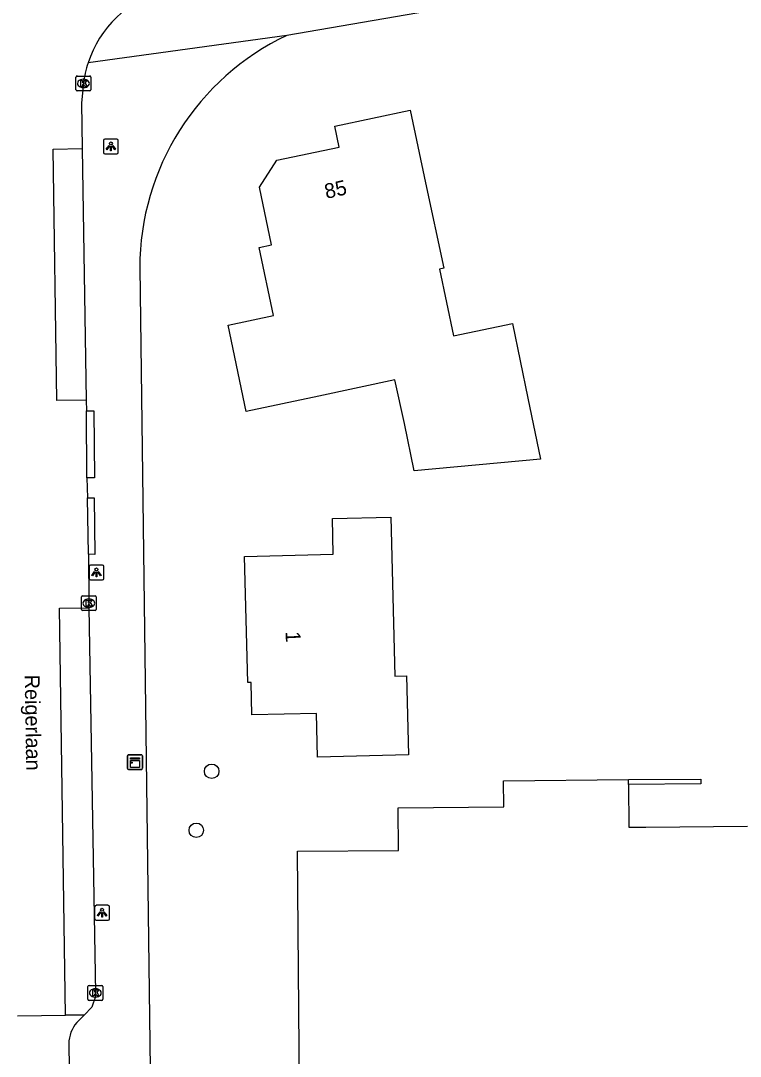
# Model space of a CAD drawing. Extents: x 161772 to 163123, y 383092 to 383917.
# Drawn here: x 162280 to 162328.5, y 383555.7 to 383625.5 of the extents above; entities that cross this region are included whole.
import ezdxf

# ---------------------------------------------------------------- set-up
doc = ezdxf.new("R2010")
doc.units = 0
for name, color, linetype in [('IMGEO_Boom', 7, 'Continuous'), ('IMGEO_Kast', 7, 'Continuous'), ('IMGEO_Kolk', 7, 'Continuous'), ('IMGEO_Lichtpunt', 7, 'Continuous'), ('IMGEO_Muur', 7, 'Continuous'), ('IMGEO_Openbare_ruimte_label', 7, 'Continuous'), ('IMGEO_Pand', 7, 'Continuous'), ('IMGEO_Pand_nummerreeks', 7, 'Continuous'), ('IMGEO_Rijbaan_lokaal_gesloten', 7, 'Continuous'), ('IMGEO_Rijbaan_lokaal_open', 7, 'Continuous'), ('IMGEO_Voetpad_open', 7, 'Continuous')]:
    doc.layers.add(name, color=color, linetype=linetype)

msp = doc.modelspace()

# ---------------------------------------------------------------- linework, layer by layer
at = {"layer": 'IMGEO_Boom'}
for centre in [(162292.877, 383574.894), (162291.839, 383570.913)]:
    msp.add_circle(centre, 0.489, dxfattribs=at)
at = {"layer": 'IMGEO_Kast'}
for p, q in [((162287.207, 383575.086), (162287.207, 383575.927)), ((162287.207, 383575.927), (162287.207, 383575.086)), ((162287.282, 383576.011), (162288.123, 383576.011)), ((162288.123, 383576.011), (162287.282, 383576.011)), ((162288.207, 383575.936), (162288.207, 383575.095)), ((162288.207, 383575.095), (162288.207, 383575.936)), ((162288.132, 383575.011), (162287.291, 383575.011)), ((162287.291, 383575.011), (162288.132, 383575.011))]:
    msp.add_line(p, q, dxfattribs=at)
for points in [[(162287.402, 383575.801), (162288.002, 383575.801), (162288.002, 383575.716), (162287.402, 383575.716), (162287.402, 383575.801)], [(162287.402, 383575.626), (162288.002, 383575.626), (162288.002, 383575.137), (162287.402, 383575.137), (162287.402, 383575.626)]]:
    msp.add_lwpolyline(points, dxfattribs=at)
msp.add_circle((162287.486, 383575.475), 0.0377, dxfattribs=at)
for centre, start, end in [((162287.285, 383575.933), 92.4484, 184.28452), ((162287.285, 383575.933), 92.4484, 184.28452), ((162288.129, 383575.933), 2.4484, 94.28452), ((162288.129, 383575.933), 2.4484, 94.28452), ((162287.285, 383575.089), 182.4484, 274.28452), ((162287.285, 383575.089), 182.4484, 274.28452), ((162288.129, 383575.089), 272.4484, 4.28452), ((162288.129, 383575.089), 272.4484, 4.28452)]:
    msp.add_arc(centre, 0.0779, start, end, dxfattribs=at)
at = {"layer": 'IMGEO_Kolk'}
for p, q in [((162283.732, 383620.873), (162283.732, 383621.725)), ((162283.807, 383621.799), (162284.659, 383621.799)), ((162284.22, 383621.579), (162284.245, 383621.579)), ((162284.733, 383621.725), (162284.733, 383620.873)), ((162284.659, 383620.799), (162283.807, 383620.799)), ((162284.243, 383621.019), (162284.218, 383621.019)), ((162284.098, 383585.81), (162284.098, 383586.662)), ((162284.173, 383586.736), (162285.025, 383586.736)), ((162284.586, 383586.516), (162284.611, 383586.516)), ((162285.099, 383586.662), (162285.099, 383585.81)), ((162285.025, 383585.736), (162284.173, 383585.736)), ((162284.609, 383585.956), (162284.584, 383585.956)), ((162284.537, 383559.512), (162284.537, 383560.364)), ((162284.612, 383560.438), (162285.464, 383560.438)), ((162285.538, 383560.364), (162285.538, 383559.512)), ((162285.048, 383559.658), (162285.023, 383559.658)), ((162285.025, 383560.218), (162285.05, 383560.218)), ((162285.464, 383559.438), (162284.612, 383559.438))]:
    msp.add_line(p, q, dxfattribs=at)
for points in [[(162283.732, 383620.873), (162283.732, 383621.725)], [(162283.807, 383621.799), (162284.659, 383621.799)], [(162284.053, 383621.499), (162284.176, 383621.499), (162284.176, 383621.348), (162284.306, 383621.499), (162284.47, 383621.499), (162284.324, 383621.348), (162284.477, 383621.099), (162284.325, 383621.099), (162284.24, 383621.263), (162284.176, 383621.196), (162284.176, 383621.099), (162284.053, 383621.099), (162284.053, 383621.499)], [(162284.733, 383621.725), (162284.733, 383620.873)], [(162284.659, 383620.799), (162283.807, 383620.799)], [(162284.098, 383585.81), (162284.098, 383586.662)], [(162284.173, 383586.736), (162285.025, 383586.736)], [(162284.419, 383586.436), (162284.542, 383586.436), (162284.542, 383586.285), (162284.672, 383586.436), (162284.836, 383586.436), (162284.69, 383586.285), (162284.843, 383586.036), (162284.691, 383586.036), (162284.606, 383586.2), (162284.542, 383586.133), (162284.542, 383586.036), (162284.419, 383586.036), (162284.419, 383586.436)], [(162285.099, 383586.662), (162285.099, 383585.81)], [(162285.025, 383585.736), (162284.173, 383585.736)], [(162284.537, 383559.512), (162284.537, 383560.364)], [(162284.612, 383560.438), (162285.464, 383560.438)], [(162285.538, 383560.364), (162285.538, 383559.512)], [(162284.858, 383560.138), (162284.981, 383560.138), (162284.981, 383559.987), (162285.111, 383560.138), (162285.275, 383560.138), (162285.129, 383559.987), (162285.282, 383559.738), (162285.13, 383559.738), (162285.045, 383559.902), (162284.981, 383559.835), (162284.981, 383559.738), (162284.858, 383559.738), (162284.858, 383560.138)], [(162285.464, 383559.438), (162284.612, 383559.438)]]:
    msp.add_lwpolyline(points, dxfattribs=at)
for centre, start, end in [((162283.809, 383621.723), 91.55205, 178.44795), ((162283.809, 383621.723), 91.55205, 178.44795), ((162284.657, 383621.723), 1.55205, 88.44795), ((162284.657, 383621.723), 1.55205, 88.44795), ((162283.809, 383620.875), 181.55205, 268.44795), ((162283.809, 383620.875), 181.55205, 268.44795), ((162284.657, 383620.875), 271.55205, 358.44795), ((162284.657, 383620.875), 271.55205, 358.44795), ((162284.175, 383586.66), 91.55205, 178.44795), ((162284.175, 383586.66), 91.55205, 178.44795), ((162285.023, 383586.66), 1.55205, 88.44795), ((162285.023, 383586.66), 1.55205, 88.44795), ((162284.175, 383585.812), 181.55205, 268.44795), ((162284.175, 383585.812), 181.55205, 268.44795), ((162285.023, 383585.812), 271.55205, 358.44795), ((162285.023, 383585.812), 271.55205, 358.44795), ((162284.614, 383560.362), 91.55205, 178.44795), ((162284.614, 383560.362), 91.55205, 178.44795), ((162285.462, 383560.362), 1.55205, 88.44795), ((162285.462, 383560.362), 1.55205, 88.44795), ((162284.614, 383559.514), 181.55205, 268.44795), ((162284.614, 383559.514), 181.55205, 268.44795), ((162285.462, 383559.514), 271.55205, 358.44795), ((162285.462, 383559.514), 271.55205, 358.44795)]:
    msp.add_arc(centre, 0.0765, start, end, dxfattribs=at)
for centre, major_axis, ratio, start_param, end_param in [((162284.219, 383621.299), (-0.387, 0.002), 0.722429, 4.712389, 7.853982), ((162284.244, 383621.299), (-0.39, 0.002), 0.717154, 1.570796, 4.712389), ((162284.585, 383586.236), (-0.387, 0.002), 0.722429, 4.712389, 7.853982), ((162284.61, 383586.236), (-0.39, 0.002), 0.717154, 1.570796, 4.712389), ((162285.024, 383559.938), (-0.387, 0.002), 0.722429, 4.712389, 7.853982), ((162285.049, 383559.938), (-0.39, 0.002), 0.717154, 1.570796, 4.712389)]:
    msp.add_ellipse(centre, major_axis=major_axis, ratio=ratio, start_param=start_param, end_param=end_param, dxfattribs=at)
at = {"layer": 'IMGEO_Lichtpunt'}
for p, q in [((162285.586, 383617.451), (162285.586, 383616.644)), ((162285.586, 383617.451), (162285.586, 383616.644)), ((162286.488, 383617.546), (162285.68, 383617.546)), ((162286.488, 383617.546), (162285.68, 383617.546)), ((162286.582, 383616.644), (162286.582, 383617.451)), ((162286.582, 383616.644), (162286.582, 383617.451)), ((162285.68, 383616.55), (162286.488, 383616.55)), ((162285.68, 383616.55), (162286.488, 383616.55)), ((162284.613, 383588.711), (162284.613, 383587.904)), ((162284.613, 383588.711), (162284.613, 383587.904)), ((162285.515, 383588.806), (162284.707, 383588.806)), ((162285.515, 383588.806), (162284.707, 383588.806)), ((162285.609, 383587.904), (162285.609, 383588.711)), ((162285.609, 383587.904), (162285.609, 383588.711)), ((162284.707, 383587.81), (162285.515, 383587.81)), ((162284.707, 383587.81), (162285.515, 383587.81)), ((162284.99, 383565.754), (162284.99, 383564.947)), ((162284.99, 383565.754), (162284.99, 383564.947)), ((162285.892, 383565.849), (162285.084, 383565.849)), ((162285.892, 383565.849), (162285.084, 383565.849)), ((162285.986, 383564.947), (162285.986, 383565.754)), ((162285.986, 383564.947), (162285.986, 383565.754)), ((162285.084, 383564.853), (162285.892, 383564.853)), ((162285.084, 383564.853), (162285.892, 383564.853))]:
    msp.add_line(p, q, dxfattribs=at)
for points in [[(162285.96, 383617.115), (162285.999, 383617.087), (162285.811, 383616.825), (162285.773, 383616.852), (162285.96, 383617.115)], [(162286.062, 383617.067), (162286.109, 383617.067), (162286.109, 383616.745), (162286.062, 383616.745), (162286.062, 383617.067)], [(162286.172, 383617.087), (162286.21, 383617.114), (162286.397, 383616.852), (162286.358, 383616.824), (162286.172, 383617.087)], [(162284.987, 383588.375), (162285.026, 383588.347), (162284.838, 383588.085), (162284.8, 383588.112), (162284.987, 383588.375)], [(162285.089, 383588.327), (162285.136, 383588.327), (162285.136, 383588.005), (162285.089, 383588.005), (162285.089, 383588.327)], [(162285.199, 383588.347), (162285.237, 383588.374), (162285.424, 383588.112), (162285.385, 383588.084), (162285.199, 383588.347)], [(162285.364, 383565.418), (162285.403, 383565.39), (162285.215, 383565.128), (162285.177, 383565.155), (162285.364, 383565.418)], [(162285.466, 383565.37), (162285.513, 383565.37), (162285.513, 383565.048), (162285.466, 383565.048), (162285.466, 383565.37)], [(162285.576, 383565.39), (162285.614, 383565.417), (162285.801, 383565.155), (162285.762, 383565.127), (162285.576, 383565.39)]]:
    msp.add_lwpolyline(points, dxfattribs=at)
for centre in [(162286.085, 383617.249), (162285.112, 383588.509), (162285.489, 383565.552)]:
    msp.add_circle(centre, 0.0994, dxfattribs=at)
for centre, start, end in [((162285.68, 383617.451), 90, 180), ((162285.68, 383617.451), 90, 180), ((162286.488, 383617.451), 0, 90), ((162286.488, 383617.451), 0, 90), ((162285.68, 383616.644), 180, 270), ((162285.68, 383616.644), 180, 270), ((162286.488, 383616.644), 270, 0), ((162286.488, 383616.644), 270, 360), ((162284.707, 383588.711), 90, 180), ((162284.707, 383588.711), 90, 180), ((162285.515, 383588.711), 0, 90), ((162285.515, 383588.711), 0, 90), ((162284.707, 383587.904), 180, 270), ((162284.707, 383587.904), 180, 270), ((162285.515, 383587.904), 270, 0), ((162285.515, 383587.904), 270, 360), ((162285.084, 383565.754), 90, 180), ((162285.084, 383565.754), 90, 180), ((162285.892, 383565.754), 0, 90), ((162285.892, 383565.754), 0, 90), ((162285.084, 383564.947), 180, 270), ((162285.084, 383564.947), 180, 270), ((162285.892, 383564.947), 270, 0), ((162285.892, 383564.947), 270, 360)]:
    msp.add_arc(centre, 0.0946, start, end, dxfattribs=at)
at = {"layer": 'IMGEO_Muur'}
msp.add_lwpolyline([(162320.969, 383574.327), (162325.839, 383574.37), (162325.842, 383574.055), (162320.972, 383574.012)], dxfattribs=at)
at = {"layer": 'IMGEO_Pand'}
for points in [[(162314.195, 383600.057), (162315.037, 383595.959), (162306.525, 383595.154), (162305.869, 383598.345), (162305.223, 383601.293), (162300.104, 383600.21), (162295.212, 383599.175), (162293.981, 383604.993), (162297.043, 383605.641), (162296.072, 383610.23), (162296.913, 383610.408), (162296.09, 383614.299), (162297.272, 383616.116), (162301.473, 383617.005), (162301.176, 383618.412), (162306.26, 383619.488), (162307.295, 383614.597), (162308.515, 383608.832), (162308.227, 383608.771), (162309.179, 383604.271), (162313.156, 383605.112), (162314.195, 383600.057)], [(162306.153, 383576.004), (162300.015, 383575.85), (162299.941, 383578.799), (162295.592, 383578.69), (162295.537, 383580.892), (162295.307, 383580.887), (162295.093, 383589.389), (162301.077, 383589.539), (162301.017, 383591.947), (162304.95, 383592.045), (162305.219, 383581.303), (162306.019, 383581.323), (162306.153, 383576.004)], [(162337.976, 383535.181), (162323.787, 383534.999), (162323.751, 383537.576), (162320.499, 383537.54), (162320.539, 383534.874), (162305.876, 383534.748), (162305.852, 383537.556), (162298.937, 383537.496), (162298.661, 383569.497), (162305.477, 383569.556), (162305.453, 383572.427), (162312.567, 383572.489), (162312.552, 383574.253), (162320.969, 383574.327)], [(162320.972, 383574.012), (162320.969, 383574.327)], [(162320.972, 383574.012), (162320.997, 383571.112), (162322.141, 383571.122), (162328.987, 383571.183)]]:
    msp.add_lwpolyline(points, dxfattribs=at)
at = {"layer": 'IMGEO_Rijbaan_lokaal_gesloten'}
for points in [[(162284.233, 383621.299), (162284.098, 383619.985), (162284.148, 383616.903)], [(162284.423, 383599.925), (162282.435, 383599.9), (162282.198, 383616.872), (162284.148, 383616.903)], [(162284.423, 383599.925), (162284.434, 383599.216)], [(162284.472, 383594.68), (162284.434, 383599.216)], [(162284.472, 383594.68), (162284.513, 383593.341)], [(162284.565, 383589.544), (162284.513, 383593.341)], [(162284.565, 383589.544), (162284.598, 383586.235), (162284.603, 383585.92)], [(162283.014, 383558.431), (162282.63, 383585.903), (162284.603, 383585.92)]]:
    msp.add_lwpolyline(points, dxfattribs=at)
for centre, radius, start, end in [((162291.752, 383620.318), 7.583, 106.51497, 161.85108), ((162291.702, 383620.332), 7.531, 161.83549, 172.62413)]:
    msp.add_arc(centre, radius, start, end, dxfattribs=at)
at = {"layer": 'IMGEO_Rijbaan_lokaal_open'}
for points in [[(162279.791, 383558.401), (162283.014, 383558.431)], [(162284.293, 383558.443), (162283.014, 383558.431)], [(162284.293, 383558.443), (162283.784, 383557.952)], [(162283.247, 383556.52), (162283.327, 383551.514)]]:
    msp.add_lwpolyline(points, dxfattribs=at)
msp.add_arc((162285.546, 383556.474), 2.3, 140.02336, 178.86455, dxfattribs=at)
at = {"layer": 'IMGEO_Voetpad_open'}
for points in [[(162423.412, 383645.583), (162412.338, 383644.315), (162376.943, 383638.143), (162297.948, 383624.537)], [(162297.948, 383624.537), (162284.546, 383622.68)], [(162284.148, 383616.903), (162284.423, 383599.925)], [(162288.026, 383608.851), (162288.936, 383539.124)], [(162284.434, 383599.216), (162284.933, 383599.22), (162284.971, 383594.684), (162284.472, 383594.68)], [(162284.513, 383593.341), (162284.951, 383593.345), (162285.01, 383589.528), (162284.565, 383589.544)], [(162284.603, 383585.92), (162285.037, 383559.938), (162285.048, 383559.704), (162284.791, 383558.983), (162284.293, 383558.443)]]:
    msp.add_lwpolyline(points, dxfattribs=at)
msp.add_arc((162305.388, 383608.85), 17.362, 115.37482, 179.99532, dxfattribs=at)

# ---------------------------------------------------------------- texts
at = {"layer": 'IMGEO_Openbare_ruimte_label'}
msp.add_text('Reigerlaan', height=1, rotation=270.91665, dxfattribs=at).set_placement((162280.275, 383581.4))
at = {"layer": 'IMGEO_Pand_nummerreeks'}
for s, rotation, p in [('85', 12.47534, (162300.604, 383613.508)), ('1', 272.67033, (162297.852, 383584.318))]:
    msp.add_text(s, height=1, rotation=rotation, dxfattribs=at).set_placement(p)

doc.saveas('drawing.dxf')
